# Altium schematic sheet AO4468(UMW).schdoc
size 127 x 101 mm
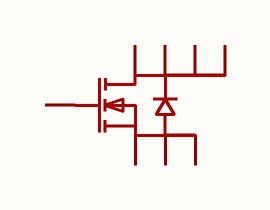
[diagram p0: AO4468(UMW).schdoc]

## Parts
Q?  ao4468(umw)  [SOIC-8_L4.9-W4.0-P1.27-LS6.0-BL]  (value not drawn)

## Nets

Not connected (* = marked no-connect by the designer): Q? 1(S) 2(S) 3(S) 4(G) 5(D) 6(D) 7(D) 8(D)

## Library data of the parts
Q? = ao4468(umw): 数量:1个N沟道;漏源电压(Vdss):30V;连续漏极电流(Id):10.5A;导通电阻(RDS(on)):14mΩ@10V;耗散功率(Pd):3.1W;阈值电压(Vgs(th)):1.8V;; Manufacturer: UMW(友台半导体); AddInBom: yes; ModelId: f04b1702bced497a80c713fe4e712e0c; ModelTransform: 192.913,238.9759,0,0,0,0,0,0,0; Number: 1个N沟道; Drain to Source Voltage: 30V; Current - Continuous Drain(Id): 10.5A; Pd - Power Dissipation: 3.1W; Gate Threshold Voltage (Vgs(th)): 1.8V; Gate Charge(Qg): 15nC@10V; Input Capacitance(Ciss): 888pF; Reverse Transfer Capacitance (Crss@Vds): 115pF; Type: N沟道; Output Capacitance(Coss): 145pF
